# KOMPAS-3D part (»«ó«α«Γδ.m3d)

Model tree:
1. Эскиз:1
2. Операция выдавливания:1
     Расстояние 1 = 4.2; Расстояние 2 = 1.6
3. Эскиз:2
4. Операция выдавливания:2
     Расстояние 1 = 0.5; Расстояние 2 = 1.6
5. Эскиз:3
6. Операция выдавливания:6
     Расстояние 1 = 0.1; Расстояние 2 = 2.4
7. Эскиз:7
8. Операция выдавливания:7
     Расстояние 1 = 0.5; Расстояние 2 = 2.4
9. Эскиз:8
10. Операция выдавливания:8
     Расстояние 1 = 4; Расстояние 2 = 2.4
11. Эскиз:9
12. Операция выдавливания:9
     Расстояние 1 = 5; Расстояние 2 = 2.4
13. Скругление:5
     Радиус = 1.5
14. Скругление:6
     Радиус = 0.2
15. Эскиз:10
16. Операция выдавливания:10
     Расстояние 1 = 5; Расстояние 2 = 2
17. Эскиз:11
18. Вырезать элемент выдавливания:2
     Расстояние 1 = 0.5
19. Эскиз:12
20. Операция выдавливания:11
     Расстояние 1 = 0.5; Расстояние 2 = 2
21. Скругление:7
     Радиус = 0.2
22. Скругление:9
     Радиус = 1
23. Эскиз:14
24. Операция выдавливания:12
     Расстояние 1 = 0.5; Расстояние 2 = 2
25. Массив по концентрической сетке:1  (with: Операция выдавливания:12)  (labels: Экземпляр ( 1, 1 ); Экземпляр ( 1, 2 ); Экземпляр ( 1, 3 ); Экземпляр ( 1, 4 ))
     N 2 = 10; Шаг 2 = 360; Номер 2 = 1
26. Скругление:10
     Радиус = 0.1
27. Скругление:11
     Радиус = 0.1

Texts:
  Сплав АЛ8  ГОСТ 1583-93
